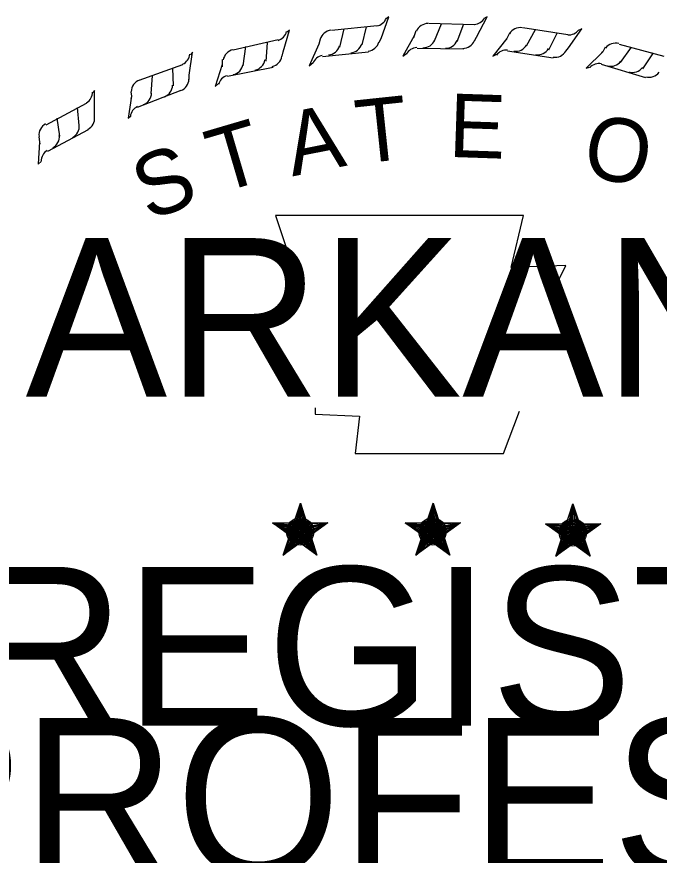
# Model space of a CAD drawing. Extents: x -1771525.8 to -1771491.7, y -422628.7 to -422606.9.
# Drawn here: x -1771500.67 to -1771499.911, y -422626.398 to -422625.408 of the extents above; entities that cross this region are included whole.
import ezdxf

# ---------------------------------------------------------------- set-up
doc = ezdxf.new("R2010")
doc.units = 0
doc.layers.add('Border 2660-Hwy18 - Stamp-ChrisC', color=7, linetype='Continuous')

msp = doc.modelspace()

# ---------------------------------------------------------------- linework, layer by layer
at = {"layer": 'Border 2660-Hwy18 - Stamp-ChrisC'}
for p, q in [((-1771500.23972, -422625.43323), (-1771500.23072, -422625.40773)), ((-1771500.23072, -422625.40773), (-1771500.23372, -422625.41003)), ((-1771500.12722, -422625.43173), (-1771500.11452, -422625.40773)), ((-1771500.11452, -422625.40773), (-1771500.11752, -422625.40923)), ((-1771500.29822, -422625.42353), (-1771500.24422, -422625.41823)), ((-1771500.26222, -422625.44073), (-1771500.25702, -422625.41973)), ((-1771500.18352, -422625.41523), (-1771500.12952, -422625.41673)), ((-1771500.17672, -422625.43623), (-1771500.16852, -422625.41603)), ((-1771500.14972, -422625.43703), (-1771500.14222, -422625.41603)), ((-1771500.35522, -422625.44903), (-1771500.34772, -422625.42353)), ((-1771500.34772, -422625.42353), (-1771500.35072, -422625.42573)), ((-1771500.28852, -422625.44373), (-1771500.28322, -422625.42203)), ((-1771500.19852, -422625.42423), (-1771500.20072, -422625.43023)), ((-1771500.08822, -422625.42723), (-1771500.09122, -422625.43323)), ((-1771500.07252, -422625.42053), (-1771500.01922, -422625.42873)), ((-1771500.06802, -422625.44223), (-1771500.05752, -422625.42273)), ((-1771500.04172, -422625.44673), (-1771500.03202, -422625.42723)), ((-1771500.01852, -422625.44453), (-1771500.00272, -422625.42203)), ((-1771500.00272, -422625.42203), (-1771500.00572, -422625.42353)), ((-1771500.41452, -422625.44673), (-1771500.36122, -422625.43473)), ((-1771500.37552, -422625.46023), (-1771500.37402, -422625.43853)), ((-1771500.31172, -422625.43403), (-1771500.31322, -422625.44003)), ((-1771500.24202, -422625.43773), (-1771500.23972, -422625.43323)), ((-1771500.20072, -422625.43023), (-1771500.21422, -422625.45423)), ((-1771500.20072, -422625.43023), (-1771500.20152, -422625.43253)), ((-1771500.12952, -422625.43623), (-1771500.12722, -422625.43173)), ((-1771500.09122, -422625.43323), (-1771500.10772, -422625.45423)), ((-1771500.09122, -422625.43323), (-1771500.09202, -422625.43473)), ((-1771500.46622, -422625.47673), (-1771500.46252, -422625.44973)), ((-1771500.46252, -422625.44973), (-1771500.46472, -422625.45273)), ((-1771500.40252, -422625.46553), (-1771500.39952, -422625.44303)), ((-1771500.35672, -422625.45423), (-1771500.35522, -422625.44903)), ((-1771500.31322, -422625.44003), (-1771500.32452, -422625.46553)), ((-1771500.31322, -422625.44003), (-1771500.31402, -422625.44223)), ((-1771500.25472, -422625.44973), (-1771500.30872, -422625.45503)), ((-1771500.14222, -422625.44603), (-1771500.19702, -422625.44523)), ((-1771500.03652, -422625.45653), (-1771500.09052, -422625.44823)), ((-1771500.02152, -422625.44823), (-1771500.01852, -422625.44453)), ((-1771499.97802, -422625.44903), (-1771499.99752, -422625.46853)), ((-1771499.97802, -422625.44903), (-1771499.97952, -422625.45053)), ((-1771499.97502, -422625.44373), (-1771499.97802, -422625.44903)), ((-1771499.95852, -422625.44003), (-1771499.90602, -422625.45423)), ((-1771499.95702, -422625.46173), (-1771499.94422, -422625.44373)), ((-1771500.42722, -422625.45803), (-1771500.42722, -422625.46403)), ((-1771500.21422, -422625.45423), (-1771500.20972, -422625.45123)), ((-1771500.10772, -422625.45423), (-1771500.10322, -422625.45203)), ((-1771499.93072, -422625.46923), (-1771499.91802, -422625.45053)), ((-1771500.52552, -422625.48273), (-1771500.47372, -422625.46403)), ((-1771500.48502, -422625.48953), (-1771500.48572, -422625.46853)), ((-1771500.42722, -422625.46403), (-1771500.43552, -422625.49023)), ((-1771500.42722, -422625.46403), (-1771500.42722, -422625.46703)), ((-1771500.36722, -422625.46773), (-1771500.42122, -422625.47823)), ((-1771500.32452, -422625.46553), (-1771500.32002, -422625.46173)), ((-1771499.99752, -422625.46853), (-1771499.99222, -422625.46703)), ((-1771499.92702, -422625.47973), (-1771499.97952, -422625.46403)), ((-1771500.51122, -422625.49853), (-1771500.50972, -422625.47753)), ((-1771500.46622, -422625.48203), (-1771500.46622, -422625.47673)), ((-1771500.43552, -422625.49023), (-1771500.43172, -422625.48653)), ((-1771500.57802, -422625.49473), (-1771500.58022, -422625.49703)), ((-1771500.57802, -422625.52103), (-1771500.57802, -422625.49473)), ((-1771500.53522, -422625.49623), (-1771500.53452, -422625.50153)), ((-1771500.47602, -422625.49473), (-1771500.52772, -422625.51503)), ((-1771500.53452, -422625.50153), (-1771500.53822, -422625.52773)), ((-1771500.53452, -422625.50153), (-1771500.53522, -422625.50453)), ((-1771500.63502, -422625.53523), (-1771500.58772, -422625.50973)), ((-1771500.59602, -422625.53603), (-1771500.59822, -422625.51503)), ((-1771500.61922, -422625.54873), (-1771500.62222, -422625.52773)), ((-1771500.57802, -422625.52623), (-1771500.57802, -422625.52103)), ((-1771500.53822, -422625.52773), (-1771500.53522, -422625.52473)), ((-1771500.58552, -422625.54123), (-1771500.63352, -422625.56673)), ((-1771500.64322, -422625.55553), (-1771500.64472, -422625.58173)), ((-1771500.64402, -422625.54953), (-1771500.64322, -422625.55553)), ((-1771500.64322, -422625.55553), (-1771500.64252, -422625.55773)), ((-1771500.64472, -422625.58173), (-1771500.64102, -422625.57873)), ((-1771500.33502, -422625.98223), (-1771500.34022, -422626.00473)), ((-1771500.33502, -422625.98223), (-1771500.33872, -422626.00553)), ((-1771500.33502, -422625.98223), (-1771500.33652, -422626.00553)), ((-1771500.33502, -422626.01603), (-1771500.33502, -422625.98223)), ((-1771500.33502, -422625.98223), (-1771500.32902, -422626.00553)), ((-1771500.33502, -422625.98223), (-1771500.33052, -422626.00553)), ((-1771500.33502, -422625.98223), (-1771500.33272, -422626.00553)), ((-1771500.17822, -422625.98223), (-1771500.18422, -422626.00473)), ((-1771500.17822, -422625.98223), (-1771500.18202, -422626.00553)), ((-1771500.17822, -422625.98223), (-1771500.18052, -422626.00553)), ((-1771500.17822, -422626.01603), (-1771500.17822, -422625.98223)), ((-1771500.17822, -422625.98223), (-1771500.17222, -422626.00553)), ((-1771500.17822, -422625.98223), (-1771500.17372, -422626.00553)), ((-1771500.17822, -422625.98223), (-1771500.17672, -422626.00553)), ((-1771500.01322, -422625.98303), (-1771500.01852, -422626.00623)), ((-1771500.01322, -422625.98303), (-1771500.01702, -422626.00623)), ((-1771500.01322, -422625.98303), (-1771500.01472, -422626.00623)), ((-1771500.01322, -422626.01753), (-1771500.01322, -422625.98303)), ((-1771500.01322, -422625.98303), (-1771500.00652, -422626.00623)), ((-1771500.01322, -422625.98303), (-1771500.00802, -422626.00623)), ((-1771500.01322, -422625.98303), (-1771500.01102, -422626.00623)), ((-1771500.36802, -422626.00553), (-1771500.33502, -422626.01603)), ((-1771500.36802, -422626.00553), (-1771500.34402, -422626.00853)), ((-1771500.36802, -422626.00553), (-1771500.34402, -422626.01003)), ((-1771500.36802, -422626.00553), (-1771500.34472, -422626.01153)), ((-1771500.36802, -422626.00553), (-1771500.34552, -422626.01523)), ((-1771500.36802, -422626.00553), (-1771500.34552, -422626.01753)), ((-1771500.36802, -422626.00553), (-1771500.34552, -422626.01973)), ((-1771500.30272, -422626.00553), (-1771500.33502, -422626.01603)), ((-1771500.30272, -422626.00553), (-1771500.33122, -422626.00773)), ((-1771500.30272, -422626.00553), (-1771500.32902, -422626.01073)), ((-1771500.30272, -422626.00553), (-1771500.32902, -422626.01223)), ((-1771500.30272, -422626.00553), (-1771500.32302, -422626.01453)), ((-1771500.30272, -422626.00553), (-1771500.32152, -422626.01523)), ((-1771500.30272, -422626.00553), (-1771500.32002, -422626.01673)), ((-1771500.21122, -422626.00553), (-1771500.17822, -422626.01603)), ((-1771500.21122, -422626.00553), (-1771500.18722, -422626.00853)), ((-1771500.21122, -422626.00553), (-1771500.18802, -422626.01003)), ((-1771500.21122, -422626.00553), (-1771500.18802, -422626.01153)), ((-1771500.21122, -422626.00553), (-1771500.18872, -422626.01523)), ((-1771500.21122, -422626.00553), (-1771500.18952, -422626.01753)), ((-1771500.21122, -422626.00553), (-1771500.18952, -422626.01973)), ((-1771500.14602, -422626.00553), (-1771500.17822, -422626.01603)), ((-1771500.14602, -422626.00553), (-1771500.17452, -422626.00773)), ((-1771500.14602, -422626.00553), (-1771500.17302, -422626.01073)), ((-1771500.14602, -422626.00553), (-1771500.17302, -422626.01223)), ((-1771500.14602, -422626.00553), (-1771500.16702, -422626.01453)), ((-1771500.14602, -422626.00553), (-1771500.16552, -422626.01523)), ((-1771500.14602, -422626.00553), (-1771500.16402, -422626.01673)), ((-1771500.04552, -422626.00703), (-1771500.01322, -422626.01753)), ((-1771500.04552, -422626.00703), (-1771500.02152, -422626.00923)), ((-1771500.04552, -422626.00703), (-1771500.02152, -422626.01073)), ((-1771500.04552, -422626.00703), (-1771500.02302, -422626.01303)), ((-1771500.04552, -422626.00703), (-1771500.02302, -422626.01603)), ((-1771500.04552, -422626.00703), (-1771500.02372, -422626.01823)), ((-1771500.04552, -422626.00703), (-1771500.02372, -422626.02053)), ((-1771499.98022, -422626.00703), (-1771500.01322, -422626.01753)), ((-1771499.98022, -422626.00703), (-1771500.00952, -422626.00923)), ((-1771499.98022, -422626.00703), (-1771500.00722, -422626.01153)), ((-1771499.98022, -422626.00703), (-1771500.00722, -422626.01303)), ((-1771499.98022, -422626.00703), (-1771500.00122, -422626.01523)), ((-1771499.98022, -422626.00703), (-1771499.99972, -422626.01673)), ((-1771499.98022, -422626.00703), (-1771499.99822, -422626.01753)), ((-1771500.35522, -422626.04373), (-1771500.33502, -422626.01603)), ((-1771500.35522, -422626.04373), (-1771500.34472, -422626.01823)), ((-1771500.35522, -422626.04373), (-1771500.34322, -422626.02123)), ((-1771500.35522, -422626.04373), (-1771500.34172, -422626.02203)), ((-1771500.35522, -422626.04373), (-1771500.33502, -422626.02353)), ((-1771500.35522, -422626.04373), (-1771500.33872, -422626.02423)), ((-1771500.31552, -422626.04373), (-1771500.33502, -422626.01603)), ((-1771500.31552, -422626.04373), (-1771500.33502, -422626.02423)), ((-1771500.31552, -422626.04373), (-1771500.33202, -422626.02423)), ((-1771500.31552, -422626.04373), (-1771500.32902, -422626.02123)), ((-1771500.31552, -422626.04373), (-1771500.32822, -422626.01673)), ((-1771500.31552, -422626.04373), (-1771500.32602, -422626.01673)), ((-1771500.19852, -422626.04373), (-1771500.17822, -422626.01603)), ((-1771500.19852, -422626.04373), (-1771500.18802, -422626.01823)), ((-1771500.19852, -422626.04373), (-1771500.18722, -422626.02123)), ((-1771500.19852, -422626.04373), (-1771500.18502, -422626.02203)), ((-1771500.19852, -422626.04373), (-1771500.17902, -422626.02353)), ((-1771500.19852, -422626.04373), (-1771500.18202, -422626.02423)), ((-1771500.15872, -422626.04373), (-1771500.17902, -422626.02423)), ((-1771500.15872, -422626.04373), (-1771500.17822, -422626.01603)), ((-1771500.15872, -422626.04373), (-1771500.17522, -422626.02423)), ((-1771500.15872, -422626.04373), (-1771500.17222, -422626.02123)), ((-1771500.15872, -422626.04373), (-1771500.17152, -422626.01673)), ((-1771500.15872, -422626.04373), (-1771500.16922, -422626.01673)), ((-1771500.03352, -422626.04523), (-1771500.01322, -422626.01753)), ((-1771500.03352, -422626.04523), (-1771500.02302, -422626.01973)), ((-1771500.03352, -422626.04523), (-1771500.02152, -422626.02203)), ((-1771500.03352, -422626.04523), (-1771500.01922, -422626.02273)), ((-1771499.99302, -422626.04523), (-1771500.01322, -422626.01753)), ((-1771499.99302, -422626.04523), (-1771500.00652, -422626.02203)), ((-1771499.99302, -422626.04523), (-1771500.00572, -422626.01823)), ((-1771499.99302, -422626.04523), (-1771500.00352, -422626.01753)), ((-1771500.35522, -422626.04373), (-1771500.33502, -422626.02653)), ((-1771500.31552, -422626.04373), (-1771500.33502, -422626.02653)), ((-1771500.19852, -422626.04373), (-1771500.17822, -422626.02653)), ((-1771500.15872, -422626.04373), (-1771500.17902, -422626.02653)), ((-1771500.03352, -422626.04523), (-1771500.01322, -422626.02503)), ((-1771500.03352, -422626.04523), (-1771500.01702, -422626.02573)), ((-1771500.03352, -422626.04523), (-1771500.01252, -422626.02723)), ((-1771499.99302, -422626.04523), (-1771500.01322, -422626.02503)), ((-1771499.99302, -422626.04523), (-1771500.01322, -422626.02803)), ((-1771499.99302, -422626.04523), (-1771500.00952, -422626.02573))]:
    msp.add_line(p, q, dxfattribs=at)
for points in [[(-1771500.36422, -422625.64253), (-1771500.33872, -422625.71973)], [(-1771500.03502, -422625.72873), (-1771500.02152, -422625.70173), (-1771500.08602, -422625.70403), (-1771500.07172, -422625.64253), (-1771500.36422, -422625.64253)], [(-1771500.31772, -422625.86973), (-1771500.31772, -422625.87723), (-1771500.26522, -422625.87953), (-1771500.27052, -422625.92373), (-1771500.09502, -422625.92373), (-1771500.07622, -422625.87353)], [(-1771500.33502, -422625.98223), (-1771500.31552, -422626.04373), (-1771500.36802, -422626.00553), (-1771500.30272, -422626.00553), (-1771500.35522, -422626.04373), (-1771500.33502, -422625.98223)], [(-1771500.17822, -422625.98223), (-1771500.15872, -422626.04373), (-1771500.21122, -422626.00553), (-1771500.14602, -422626.00553), (-1771500.19852, -422626.04373), (-1771500.17822, -422625.98223)], [(-1771500.01322, -422625.98303), (-1771499.99302, -422626.04523), (-1771500.04552, -422626.00703), (-1771499.98022, -422626.00703), (-1771500.03352, -422626.04523), (-1771500.01322, -422625.98303)]]:
    msp.add_lwpolyline(points, dxfattribs=at)
for centre, radius in [((-1771500.33538, -422626.01595), 0.01615), ((-1771500.33538, -422626.01595), 0.01462), ((-1771500.33538, -422626.01595), 0.01355), ((-1771500.33538, -422626.01595), 0.01245), ((-1771500.17891, -422626.01595), 0.01615), ((-1771500.17891, -422626.01595), 0.01462), ((-1771500.17891, -422626.01595), 0.01355), ((-1771500.17891, -422626.01595), 0.01245), ((-1771500.01324, -422626.01704), 0.01615), ((-1771500.01324, -422626.01704), 0.01462), ((-1771500.01324, -422626.01704), 0.01355), ((-1771500.33538, -422626.01595), 0.01085), ((-1771500.33538, -422626.01595), 0.01008), ((-1771500.33538, -422626.01595), 0.00929), ((-1771500.33538, -422626.01595), 0.008), ((-1771500.33538, -422626.01595), 0.00701), ((-1771500.33538, -422626.01595), 0.00583), ((-1771500.33538, -422626.01595), 0.00464), ((-1771500.33538, -422626.01595), 0.00346), ((-1771500.33538, -422626.01595), 0.00278), ((-1771500.17891, -422626.01595), 0.01085), ((-1771500.17891, -422626.01595), 0.01008), ((-1771500.17891, -422626.01595), 0.00929), ((-1771500.17891, -422626.01595), 0.008), ((-1771500.17891, -422626.01595), 0.00701), ((-1771500.17891, -422626.01595), 0.00583), ((-1771500.17891, -422626.01595), 0.00464), ((-1771500.17891, -422626.01595), 0.00346), ((-1771500.17891, -422626.01595), 0.00278), ((-1771500.01324, -422626.01704), 0.01245), ((-1771500.01324, -422626.01704), 0.01085), ((-1771500.01324, -422626.01704), 0.01008), ((-1771500.01324, -422626.01704), 0.00929), ((-1771500.01324, -422626.01704), 0.008), ((-1771500.01324, -422626.01704), 0.00701), ((-1771500.01324, -422626.01704), 0.00583), ((-1771500.01324, -422626.01704), 0.00464), ((-1771500.01324, -422626.01704), 0.00346), ((-1771500.01324, -422626.01704), 0.00278), ((-1771500.33538, -422626.01595), 0.00135), ((-1771500.17891, -422626.01595), 0.00135), ((-1771500.01324, -422626.01704), 0.00135)]:
    msp.add_circle(centre, radius, dxfattribs=at)
for centre, start, end in [((-1771500.24732, -422625.40402), 279.92492, 338.71276), ((-1771500.13068, -422625.40198), 273.42361, 332.21146), ((-1771500.18436, -422625.4305), 89.16284, 157.53681), ((-1771500.36558, -422625.42147), 286.27006, 345.0579), ((-1771500.29743, -422625.43844), 95.66414, 164.03812), ((-1771500.07533, -422625.43541), 81.42307, 149.79704), ((-1771500.0183, -422625.41438), 265.68385, 324.47169), ((-1771500.27687, -422625.43564), 275.66414, 344.03812), ((-1771500.25645, -422625.43355), 275.66414, 344.03812), ((-1771500.19006, -422625.42956), 269.16284, 337.53681), ((-1771500.16363, -422625.43005), 269.16284, 337.53681), ((-1771500.14309, -422625.43029), 269.16284, 337.53681), ((-1771499.96305, -422625.45372), 73.99093, 142.3649), ((-1771500.41158, -422625.46121), 102.00928, 170.38325), ((-1771500.30319, -422625.43815), 275.66414, 344.03812), ((-1771500.19678, -422625.45881), 93.42361, 152.21146), ((-1771500.09144, -422625.46179), 85.68385, 144.47169), ((-1771500.08085, -422625.43371), 261.42307, 329.79704), ((-1771500.05472, -422625.43776), 261.42307, 329.79704), ((-1771500.03441, -422625.44076), 261.42307, 329.79704), ((-1771500.48027, -422625.45025), 294.83706, 353.62491), ((-1771500.39146, -422625.45616), 282.00928, 350.38325), ((-1771500.37139, -422625.45183), 282.00928, 350.38325), ((-1771500.30655, -422625.46797), 99.92492, 158.71276), ((-1771500.41734, -422625.46156), 282.00928, 350.38325), ((-1771499.98244, -422625.47779), 78.25171, 137.03955), ((-1771499.9683, -422625.45132), 253.99093, 322.3649), ((-1771499.94292, -422625.45871), 253.99093, 322.3649), ((-1771500.41739, -422625.49157), 106.27006, 165.0579), ((-1771499.92316, -422625.46432), 253.99093, 322.3649), ((-1771500.51984, -422625.4964), 110.57629, 178.95026), ((-1771500.50069, -422625.4884), 290.57629, 358.95026), ((-1771500.48149, -422625.48113), 290.57629, 358.95026), ((-1771500.59536, -422625.49682), 301.95449, 0.74233), ((-1771500.52548, -422625.4976), 290.57629, 358.95026), ((-1771500.52106, -422625.52728), 114.83706, 173.62491), ((-1771500.59275, -422625.52762), 297.69371, 6.06769), ((-1771500.62891, -422625.54751), 117.69371, 186.06769), ((-1771500.6109, -422625.53721), 297.69371, 6.06769), ((-1771500.63436, -422625.54941), 297.69371, 6.06769), ((-1771500.62629, -422625.57831), 121.95449, 180.74233)]:
    msp.add_arc(centre, 0.01481, start, end, dxfattribs=at)

# ---------------------------------------------------------------- texts
for s, height, rotation, p in [('E', 0.07499, 358.07323, (-1771500.16072, -422625.57323)), ('T', 0.075, 6.02276, (-1771500.26572, -422625.58143)), ('A', 0.075, 11.21318, (-1771500.34452, -422625.59643)), ('T', 0.07499, 16.4036, (-1771500.43152, -422625.61673)), ('O', 0.07498, 350.4515, (-1771500.00402, -422625.59573)), ('S', 0.07499, 21.59401, (-1771500.51402, -422625.64973))]:
    msp.add_text(s, height=height, rotation=rotation, dxfattribs=at).set_placement(p)
for s, height, p in [('ARKANSAS', 0.187497, (-1771500.65952, -422625.85673)), ('REGISTERED', 0.187497, (-1771500.72322, -422626.24523)), ('PROFESSIONAL', 0.1874966, (-1771500.83052, -422626.42373))]:
    msp.add_text(s, height=height, dxfattribs=at).set_placement(p)

doc.saveas('drawing.dxf')
